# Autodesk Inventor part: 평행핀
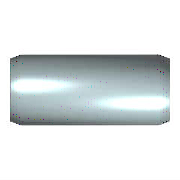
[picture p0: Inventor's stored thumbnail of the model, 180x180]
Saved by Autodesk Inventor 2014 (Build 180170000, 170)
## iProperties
IsCustomPart: 0
Created: 2009-02
Part Number: 평행핀
Material: 강, 연강
Description: 평행 핀
Document SubType Name: Modeling
Standard: KS B 1320
Designer: KYOUNG IL JANG
Standards Organization: KS
Language: ko-KR
Size Designation: B 5 x  20
Categories: <MemberInstance><Categories><Category DisplayName="조임쇠" InternalName="e4da775c-781d-43d5-af7c-5136215cf5a6" Mnemonic="FSTN"><Category DisplayName="핀" InternalNa
Density: 7.86 g/cm^3
Mass: 3.06605 g
Surface Area: 3.46755 cm^2
Volume: 0.390082 cm^3
Appearance: 강철
Author: KYOUNG IL JANG
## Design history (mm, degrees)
sketch "스케치"
  geometry: C1 r 2.5 at (0, 0); 1 further point
  constraints: 1 centre point, 1 coincident
  dimensions: "d1" = 5 diameter of C1 (= NND)
extrude "본체" new body sketch "스케치" distance "d2" = 20 (= NLG); taper "d3" = 0 deg
chamfer "스케치2" distance "d8" = 0.8 (= PHH); stored, may be unused: angle "d9" = 15 deg (= FAWI), second distance "d12" = 0.8 (= PHH)
body "Solid1"
chamfer "모따기1" distance "d4" = 0.8 (= PHH); stored, may be unused: angle "d5" = 15 deg (= FAWI), second distance "d11" = 0.8 (= PHH)
other parameters: "NND" = 5 [user parameter; used in 1 equation term], "NLG" = 20 [user parameter; used in 1 equation term], "PHH" = 0.8 [user parameter; used in 4 equation terms], "FAWI" = 15 deg [user parameter; used in 2 equation terms], "d13" = 0, "d15" = 0, "d16" = 0, "KAH" = 0.63 [user parameter]
